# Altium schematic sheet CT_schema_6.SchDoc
size 430 x 414 mm
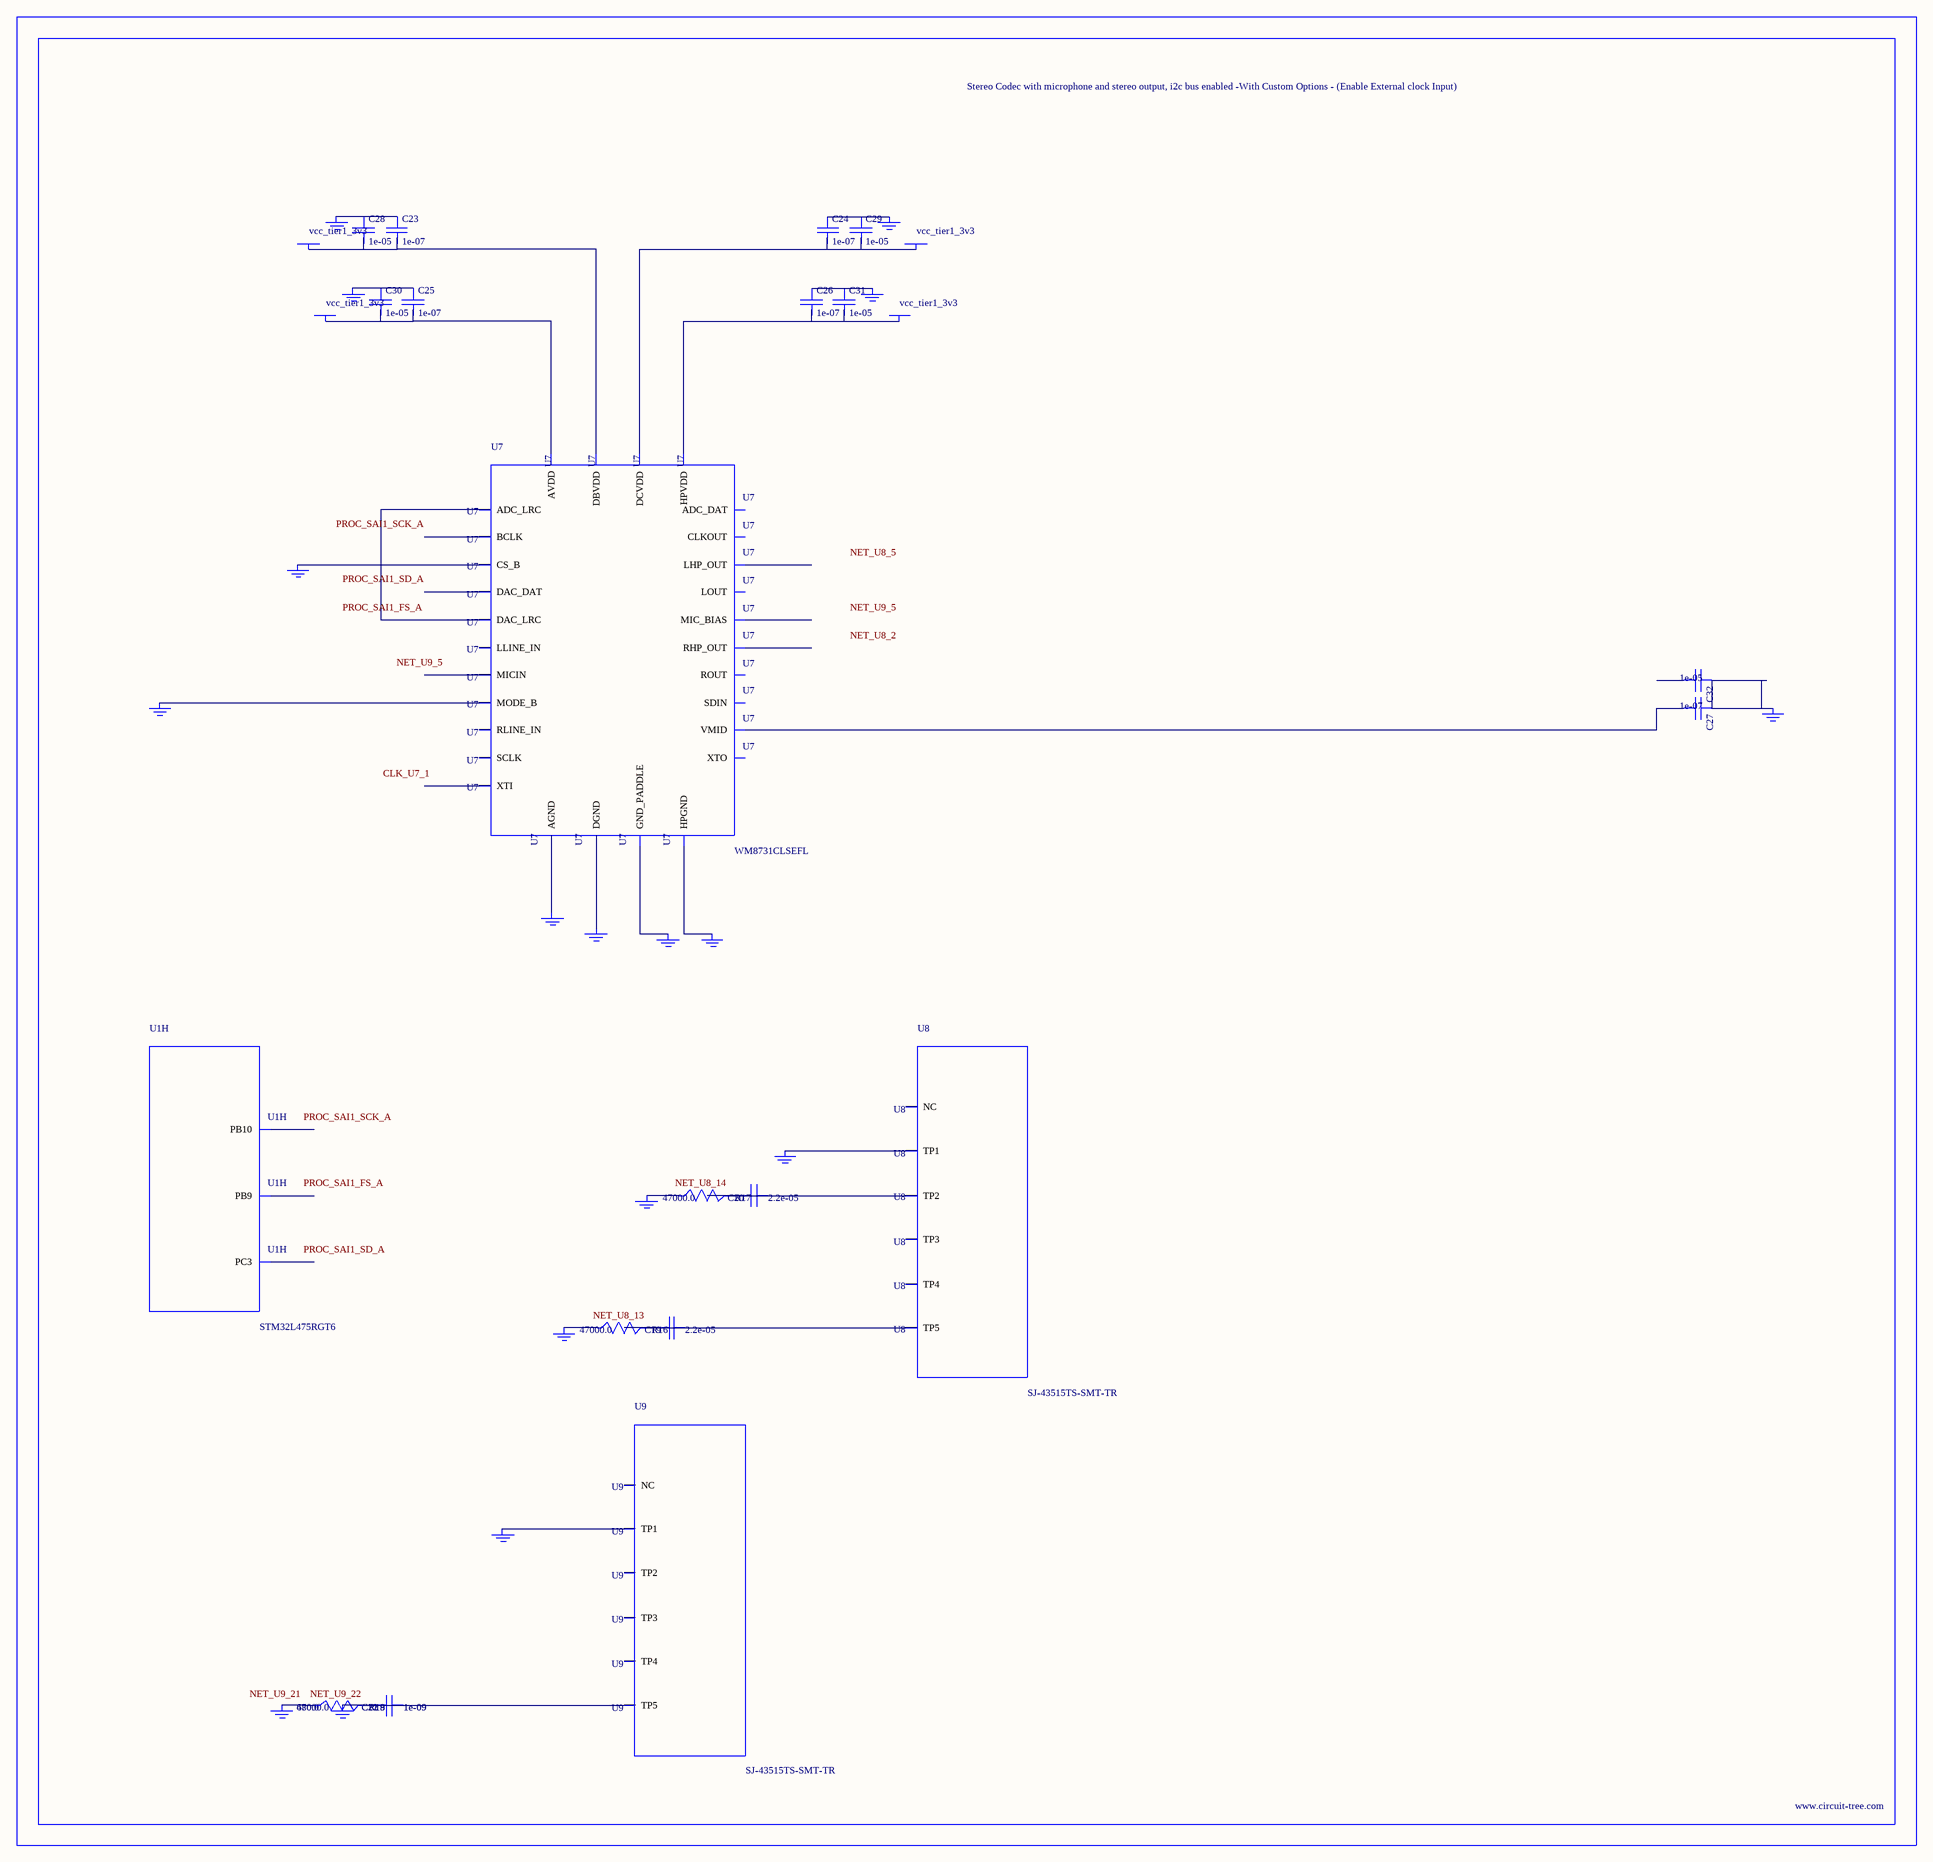
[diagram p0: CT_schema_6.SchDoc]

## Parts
BORDER5  (no value)
C19  2.2e-05  [C1210]
C20  2.2e-05  [C1210]
C21  1e-09  [C0402]
C22  1e-09  [C0402]
C23  1e-07  [C0402]
C24  1e-07  [C0402]
C25  1e-07  [C0402]
C26  1e-07  [C0402]
C27  1e-07  [C0402]
C28  1e-05  [C0805]
C29  1e-05  [C0805]
C30  1e-05  [C0805]
C31  1e-05  [C0805]
C32  1e-05  [C0805]
GND_INSTANCE_5_0  (no value)
GND_INSTANCE_5_1  (no value)
GND_INSTANCE_5_2  (no value)
GND_INSTANCE_5_3  (no value)
GND_INSTANCE_5_4  (no value)
GND_INSTANCE_5_5  (no value)
GND_INSTANCE_5_6  (no value)
GND_INSTANCE_5_7  (no value)
GND_INSTANCE_5_8  (no value)
GND_INSTANCE_5_9  (no value)
GND_INSTANCE_5_10  (no value)
GND_INSTANCE_5_11  (no value)
GND_INSTANCE_5_12  (no value)
GND_INSTANCE_5_13  (no value)
GND_INSTANCE_5_14  (no value)
GND_INSTANCE_5_15  (no value)
GND_INSTANCE_5_16  (no value)
POWER_INSTANCE_5_0  vcc_tier1_3v3
POWER_INSTANCE_5_1  vcc_tier1_3v3
POWER_INSTANCE_5_2  vcc_tier1_3v3
POWER_INSTANCE_5_3  vcc_tier1_3v3
R16  47000.0  [R0603]
R17  47000.0  [R0603]
R18  47000.0  [R0603]
R19  680.0  [R0603]
U1  STM32L475RGT6  [LQFP64]  (part H of 8)
U7  WM8731CLSEFL  [QFN-28]
U8  SJ-43515TS-SMT-TR  [SJ-43515TS-SMT-TR]
U9  SJ-43515TS-SMT-TR  [SJ-43515TS-SMT-TR]

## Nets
NetC19_1: C19.1 C19.2 R16.2 U8.5(TP5)
NetC20_1: C20.1 C20.2 R17.2 U8.2(TP2)
NetC21_1: C21.1 C21.2 C22.1 C22.2 GND_INSTANCE_5_16.0(GND) R18.2 R19.2 U9.5(TP5)
NetC23_1: C23.1 C28.1 GND_INSTANCE_5_1.0(GND)
NetC23_2: C23.2 C28.2 POWER_INSTANCE_5_1.0(PWR) U7.5(DBVDD)
NetC24_1: C24.1 C29.1 GND_INSTANCE_5_0.0(GND)
NetC24_2: C24.2 C29.2 POWER_INSTANCE_5_0.0(PWR) U7.3(DCVDD)
NetC25_1: C25.1 C30.1 GND_INSTANCE_5_4.0(GND)
NetC25_2: C25.2 C30.2 POWER_INSTANCE_5_3.0(PWR) U7.18(AVDD)
NetC26_1: C26.1 C31.1 GND_INSTANCE_5_2.0(GND)
NetC26_2: C26.2 C31.2 POWER_INSTANCE_5_2.0(PWR) U7.12(HPVDD)
NetC27_1: C27.1 C32.1 GND_INSTANCE_5_5.0(GND)
NetC27_2: C27.2 U7.20(VMID)
NetGND_INSTANCE_5_3_0: GND_INSTANCE_5_3.0(GND) U7.15(HPGND)
NetGND_INSTANCE_5_6_0: GND_INSTANCE_5_6.0(GND) U7.25(MODE_B)
NetGND_INSTANCE_5_7_0: GND_INSTANCE_5_7.0(GND) U7.26(CS_B)
NetGND_INSTANCE_5_8_0: GND_INSTANCE_5_8.0(GND) U7.29(GND_PADDLE)
NetGND_INSTANCE_5_9_0: GND_INSTANCE_5_9.0(GND) U7.4(DGND)
NetGND_INSTANCE_5_10_0: GND_INSTANCE_5_10.0(GND) U7.19(AGND)
NetGND_INSTANCE_5_11_0: GND_INSTANCE_5_11.0(GND) U8.1(TP1)
NetGND_INSTANCE_5_12_0: GND_INSTANCE_5_12.0(GND) R17.1
NetGND_INSTANCE_5_13_0: GND_INSTANCE_5_13.0(GND) R16.1
NetGND_INSTANCE_5_14_0: GND_INSTANCE_5_14.0(GND) U9.1(TP1)
NetGND_INSTANCE_5_15_0: GND_INSTANCE_5_15.0(GND) R18.1 R19.1
NetU7_9: U7.9(DAC_LRC) U7.11(ADC_LRC)

Not connected (* = marked no-connect by the designer): C32 2; U1 11(PC3) 29(PB10) 62(PB9); U7 1(XTI) 2(XTO) 6(CLKOUT) 7(BCLK) 8(DAC_DAT) 10(ADC_DAT) 13(LHP_OUT) 14(RHP_OUT) 16(LOUT) 17(ROUT) 21(MIC_BIAS) 22(MICIN) 23(RLINE_IN) 24(LLINE_IN) 27(SDIN) 28(SCLK); U8 3(TP3) 4(TP4) 6(NC); U9 2(TP2) 3(TP3) 4(TP4) 6(NC)

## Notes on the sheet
- Labels drawn without touching a wire or pin: CLK_U7_1, NET_U8_2, NET_U8_5, NET_U8_13, NET_U8_14, NET_U9_5, NET_U9_21, NET_U9_22, PROC_SAI1_FS_A, PROC_SAI1_SCK_A, PROC_SAI1_SD_A

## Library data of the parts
BORDER5 = BORDER_PAGE5
C19 C20 = C1210C224K5RACTU
C21 C22 = C0402C102K3RAC
C23-C27 = C0402C104K3RACTU
C28-C32 = C0805C106K8RACTU
GND_INSTANCE_5_0-GND_INSTANCE_5_16 = GND
POWER_INSTANCE_5_0-POWER_INSTANCE_5_3 = PWR
R16-R18 = RC0603JR-0747KL
R19 = RC0603JR-07680RL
